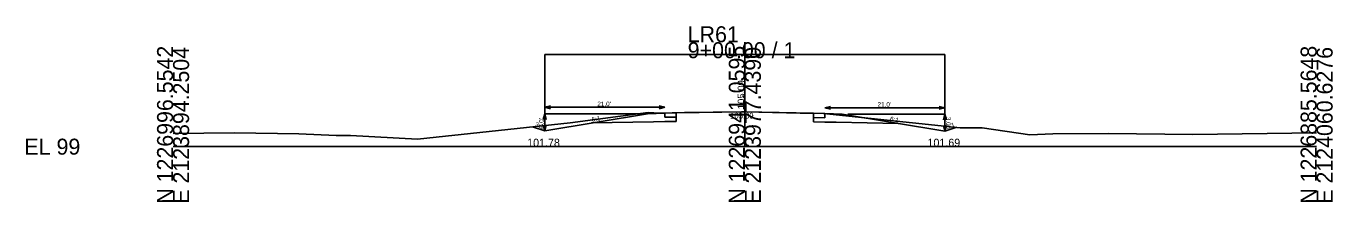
# Model space of a CAD drawing. Extents: x 2126751 to 2128979, y 1225108 to 1234639.
# Drawn here: x 2126750.9 to 2126979.4, y 1234107.5 to 1234138.4 of the extents above; entities that cross this region are included whole.
import ezdxf

# ---------------------------------------------------------------- set-up
doc = ezdxf.new("R2010")
doc.units = 0
for name, color, linetype in [('XS_CELL', 7, 'Continuous'), ('XS_M_DITCH', 7, 'Continuous'), ('XS_P_FINISHED_GRADE', 7, 'Continuous'), ('XS_P_FINISHED_GRADE_ELEV_TX', 7, 'Continuous'), ('XS_P_SUBGRADE_GRANULAR', 7, 'Continuous'), ('XS_P_SUBGRADE_LEVELING', 7, 'Continuous'), ('XS_P_SUBGRADE_PAVEMENT', 7, 'Continuous'), ('XS_P_TX_CLEARZONE', 7, 'Continuous'), ('XS_P_TX_DCH', 7, 'Continuous'), ('XS_P_TX_FS_BS', 7, 'Continuous'), ('XS_X_GROUND', 7, 'Continuous'), ('XS_X_GROUND_TX', 7, 'Continuous')]:
    doc.layers.add(name, color=color, linetype=linetype)

msp = doc.modelspace()

# ---------------------------------------------------------------- linework, layer by layer
at = {"layer": 'XS_CELL'}
for p, q in [((2126876.61, 1234117.21), (2126876.61, 1234135.52)), ((2126776.61, 1234117.21), (2126876.61, 1234117.21)), ((2126876.61, 1234117.21), (2126976.61, 1234117.21))]:
    msp.add_line(p, q, dxfattribs=at)
at = {"layer": 'XS_M_DITCH'}
for p, q in [((2126841.61, 1234119.99), (2126841.61, 1234133.39)), ((2126841.61, 1234133.39), (2126911.61, 1234133.39)), ((2126911.61, 1234133.39), (2126911.61, 1234119.9))]:
    msp.add_line(p, q, dxfattribs=at)
at = {"layer": 'XS_P_FINISHED_GRADE'}
for p, q in [((2126859.61, 1234122.99), (2126841.61, 1234119.99)), ((2126862.61, 1234123.11), (2126859.61, 1234122.99)), ((2126864.61, 1234123.15), (2126862.61, 1234123.11)), ((2126876.61, 1234123.3), (2126864.61, 1234123.15)), ((2126888.61, 1234123.06), (2126876.61, 1234123.3)), ((2126888.61, 1234123.06), (2126890.61, 1234123.02)), ((2126890.61, 1234123.02), (2126893.61, 1234122.9)), ((2126893.61, 1234122.9), (2126911.61, 1234119.9)), ((2126841.61, 1234119.99), (2126839.48, 1234120.7)), ((2126911.61, 1234119.9), (2126913.71, 1234120.6))]:
    msp.add_line(p, q, dxfattribs=at)
at = {"layer": 'XS_P_SUBGRADE_GRANULAR'}
for p, q in [((2126864.61, 1234121.65), (2126864.61, 1234122.4)), ((2126888.61, 1234121.56), (2126888.61, 1234122.31)), ((2126860.61, 1234121.57), (2126849.79, 1234121.36)), ((2126862.61, 1234121.61), (2126860.61, 1234121.57)), ((2126864.61, 1234121.65), (2126862.61, 1234121.61)), ((2126888.61, 1234121.56), (2126890.61, 1234121.52)), ((2126890.61, 1234121.52), (2126892.61, 1234121.48)), ((2126892.61, 1234121.48), (2126903.43, 1234121.26))]:
    msp.add_line(p, q, dxfattribs=at)
at = {"layer": 'XS_P_SUBGRADE_LEVELING'}
for p, q in [((2126864.61, 1234123.15), (2126866.03, 1234123.18)), ((2126866.03, 1234123.18), (2126876.05, 1234123.31)), ((2126876.05, 1234123.31), (2126876.61, 1234123.3)), ((2126876.61, 1234123.3), (2126883.92, 1234123.15)), ((2126883.92, 1234123.15), (2126888.61, 1234123.05)), ((2126888.61, 1234123.06), (2126888.61, 1234123.05))]:
    msp.add_line(p, q, dxfattribs=at)
at = {"layer": 'XS_P_SUBGRADE_PAVEMENT'}
for p, q in [((2126862.61, 1234122.36), (2126862.61, 1234123.11)), ((2126864.61, 1234122.4), (2126862.61, 1234122.36)), ((2126864.61, 1234122.4), (2126864.61, 1234123.15)), ((2126888.61, 1234122.31), (2126888.61, 1234123.05)), ((2126888.61, 1234122.31), (2126890.61, 1234122.27)), ((2126890.61, 1234122.27), (2126890.61, 1234123.02))]:
    msp.add_line(p, q, dxfattribs=at)
at = {"layer": 'XS_P_TX_CLEARZONE'}
for p, q in [((2126841.61, 1234124.11), (2126842.61, 1234124.36)), ((2126841.61, 1234124.11), (2126842.61, 1234123.86)), ((2126862.61, 1234124.11), (2126841.61, 1234124.11)), ((2126862.61, 1234124.11), (2126861.61, 1234124.36)), ((2126862.61, 1234124.11), (2126861.61, 1234123.86)), ((2126890.61, 1234124.02), (2126891.61, 1234124.27)), ((2126911.61, 1234124.02), (2126910.61, 1234124.27)), ((2126841.61, 1234122.99), (2126841.36, 1234121.99)), ((2126841.61, 1234122.99), (2126841.86, 1234121.99)), ((2126841.61, 1234122.99), (2126841.61, 1234119.99)), ((2126858.61, 1234122.99), (2126841.61, 1234122.99)), ((2126890.61, 1234124.02), (2126891.61, 1234123.77)), ((2126890.61, 1234124.02), (2126911.61, 1234124.02)), ((2126894.61, 1234122.9), (2126911.61, 1234122.9)), ((2126911.61, 1234124.02), (2126910.61, 1234123.77)), ((2126911.61, 1234122.9), (2126911.36, 1234121.9)), ((2126911.61, 1234122.9), (2126911.61, 1234119.9)), ((2126911.61, 1234122.9), (2126911.86, 1234121.9)), ((2126841.61, 1234119.99), (2126841.36, 1234120.99)), ((2126841.61, 1234119.99), (2126841.86, 1234120.99)), ((2126911.61, 1234119.9), (2126911.36, 1234120.9)), ((2126911.61, 1234119.9), (2126911.86, 1234120.9))]:
    msp.add_line(p, q, dxfattribs=at)
at = {"layer": 'XS_X_GROUND'}
for p, q in [((2126846.06, 1234121.41), (2126859.71, 1234123.21)), ((2126859.71, 1234123.21), (2126861.73, 1234123.11)), ((2126861.73, 1234123.11), (2126866.03, 1234123.18)), ((2126866.03, 1234123.18), (2126876.05, 1234123.31)), ((2126876.05, 1234123.31), (2126876.61, 1234123.3)), ((2126876.61, 1234123.3), (2126883.92, 1234123.15)), ((2126883.92, 1234123.15), (2126890.34, 1234123.01)), ((2126890.34, 1234123.01), (2126914.27, 1234120.54)), ((2126776.61, 1234119.54), (2126787.36, 1234119.66)), ((2126787.36, 1234119.66), (2126798.62, 1234119.46)), ((2126798.62, 1234119.46), (2126805.12, 1234119.19)), ((2126819.38, 1234118.55), (2126846.06, 1234121.41)), ((2126914.27, 1234120.54), (2126918.1, 1234120.53)), ((2126918.1, 1234120.53), (2126926.43, 1234119.27)), ((2126926.43, 1234119.27), (2126930.49, 1234119.48)), ((2126930.49, 1234119.48), (2126940.23, 1234119.49)), ((2126940.23, 1234119.49), (2126954.96, 1234119.33)), ((2126954.96, 1234119.33), (2126976.61, 1234119.61)), ((2126805.12, 1234119.19), (2126807.64, 1234119.14)), ((2126807.64, 1234119.14), (2126819.38, 1234118.55))]:
    msp.add_line(p, q, dxfattribs=at)

# ---------------------------------------------------------------- texts
at = {"layer": 'XS_CELL'}
for s, p in [('LR61', (2126866.61, 1234135.52)), ('9+00.00 / 1', (2126866.61, 1234132.72)), ('EL 99', (2126750.61, 1234115.81))]:
    msp.add_text(s, height=2.8, dxfattribs=at).set_placement(p)
for s, p in [('N 1226996.5542', (2126776.61, 1234107.21)), ('E 2123894.2504', (2126779.41, 1234107.21)), ('N 1226941.0595', (2126876.61, 1234107.21)), ('E 2123977.4390', (2126879.41, 1234107.21)), ('N 1226885.5648', (2126976.61, 1234107.21)), ('E 2124060.6276', (2126979.41, 1234107.21))]:
    msp.add_text(s, height=2.8, rotation=90, dxfattribs=at).set_placement(p)
at = {"layer": 'XS_P_FINISHED_GRADE_ELEV_TX'}
msp.add_text(' 105.09', height=1.25, rotation=90, dxfattribs=at).set_placement((2126876.61, 1234123.3))
at = {"layer": 'XS_P_TX_CLEARZONE'}
for p in [(2126850.82, 1234124.31), (2126899.82, 1234124.22)]:
    msp.add_text("21.0'", height=0.8, dxfattribs=at).set_placement(p)
for rotation, p in [(90, (2126841.41, 1234120.47)), (270, (2126911.81, 1234122.43))]:
    msp.add_text("3.0'", height=0.8, rotation=rotation, dxfattribs=at).set_placement(p)
at = {"layer": 'XS_P_TX_DCH'}
for s, p in [('101.78', (2126838.54, 1234117.2)), ('101.69', (2126908.55, 1234117.2))]:
    msp.add_text(s, height=1.4, dxfattribs=at).set_placement(p)
at = {"layer": 'XS_P_TX_FS_BS'}
for s, rotation, p in [('6:1', 9.4623, (2126849.89, 1234121.58)), ('6:1', 350.5377, (2126901.95, 1234121.71)), ('3:1', 341.5651, (2126839.86, 1234120.79)), ('3:1', 18.4349, (2126911.95, 1234120.22))]:
    msp.add_text(s, height=0.8, rotation=rotation, dxfattribs=at).set_placement(p)
at = {"layer": 'XS_X_GROUND_TX'}
msp.add_text('105.09', height=1, dxfattribs=at).set_placement((2126874.05, 1234122.14))

doc.saveas('drawing.dxf')
